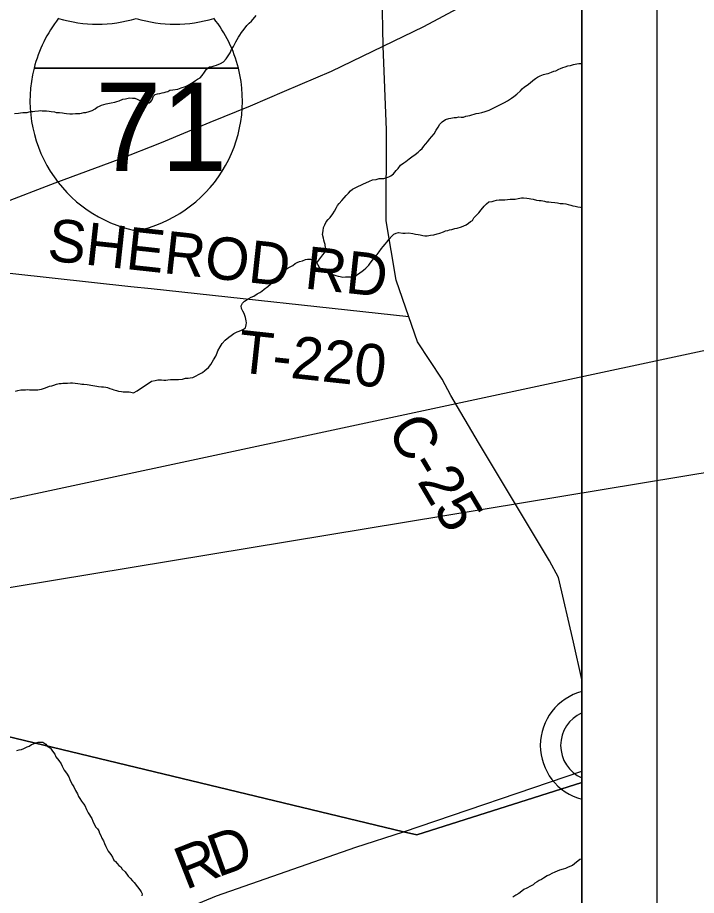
# Model space of a CAD drawing. Extents: x 0.4 to 34.4, y -2.1 to 19.9.
# Drawn here: x 9.045 to 9.953, y 15.384 to 16.558 of the extents above; entities that cross this region are included whole.
import ezdxf

# ---------------------------------------------------------------- set-up
doc = ezdxf.new("R2010")
doc.units = 0
for name, color, linetype in [('GM_X_County', 7, 'Continuous'), ('GM_X_County_Road', 7, 'Continuous'), ('GM_X_County_Road_Text', 7, 'Continuous'), ('GM_X_Interstate_Route', 7, 'Continuous'), ('GM_X_Interstate_Shield', 7, 'Continuous'), ('GM_X_Minor_River', 7, 'Continuous'), ('GM_X_Township', 7, 'Continuous'), ('GM_X_Township_Road', 7, 'Continuous'), ('GM_X_Township_Road_Text', 7, 'Continuous'), ('GM_X_Unincorporated', 7, 'Continuous'), ('SH_Data', 7, 'Continuous')]:
    doc.layers.add(name, color=color, linetype=linetype)

msp = doc.modelspace()

# ---------------------------------------------------------------- linework, layer by layer
at = {"layer": 'GM_X_County'}
msp.add_lwpolyline([(9.8001, 15.3423), (9.8001, 18.8357), (3.0001, 18.8357), (3.0001, 12.0357), (9.5074, 12.0357)], dxfattribs=at)
at = {"layer": 'GM_X_County_Road'}
for points in [[(9.8001, 15.6729), (9.789, 15.7227), (9.7688, 15.8095), (9.7566, 15.8317), (9.6617, 15.9899), (9.6248, 16.0527), (9.613, 16.0746), (9.5801, 16.1244), (9.5685, 16.1577), (9.5514, 16.2068), (9.5383, 16.2863), (9.5386, 16.4082), (9.5341, 16.5199), (9.53, 16.7315)], [(8.2275, 14.9194), (8.32, 14.9606), (8.4596, 15.0199), (8.6764, 15.1154), (8.8642, 15.1959), (9.0381, 15.2705), (9.3113, 15.3835), (9.4976, 15.4487), (9.5613, 15.4693), (9.8001, 15.5501)]]:
    msp.add_lwpolyline(points, dxfattribs=at)
at = {"layer": 'GM_X_Interstate_Route'}
msp.add_lwpolyline([(8.2799, 16.0261), (8.3601, 16.056), (8.441, 16.087), (8.5383, 16.1247), (8.6182, 16.1542), (8.7033, 16.187), (8.7839, 16.218), (8.8633, 16.2483), (8.9432, 16.2782), (9.0238, 16.3096), (9.0956, 16.3369), (9.1811, 16.3686), (9.2375, 16.3911), (9.303, 16.4181), (9.3569, 16.4399), (9.4021, 16.4597), (9.4652, 16.4866), (9.5341, 16.5199), (9.5885, 16.5462), (9.6403, 16.5738)], dxfattribs=at)
at = {"layer": 'GM_X_Interstate_Shield'}
for p, q in [((9.0673, 16.4905), (9.3406, 16.4905)), ((9.3406, 16.4905), (9.0673, 16.4905)), ((9.3406, 16.4905), (9.0673, 16.4905))]:
    msp.add_line(p, q, dxfattribs=at)
for centre, start, end in [((9.2394, 16.447), 141.669, 165.8066), ((9.152, 16.7269), 253.0091, 286.9909), ((9.2558, 16.7269), 253.0091, 286.9909), ((9.1684, 16.447), 14.1934, 38.331), ((9.2394, 16.447), 165.8066, 258.463), ((9.1684, 16.447), 281.537, 14.1934)]:
    msp.add_arc(centre, 0.1776, start, end, dxfattribs=at)
at = {"layer": 'GM_X_Minor_River'}
for points in [[(9.2495, 16.4612), (9.2529, 16.4617), (9.2594, 16.4623), (9.264, 16.4642), (9.2697, 16.466), (9.2727, 16.4675), (9.2758, 16.469), (9.28, 16.4719), (9.2831, 16.4742), (9.2858, 16.4756), (9.2896, 16.4775), (9.2923, 16.4805), (9.2954, 16.485), (9.2977, 16.4891), (9.3019, 16.4921), (9.3054, 16.4928), (9.308, 16.4936), (9.3111, 16.4943), (9.3168, 16.4969), (9.3206, 16.4991), (9.3241, 16.5028), (9.3268, 16.507), (9.3296, 16.5111), (9.3315, 16.5156), (9.3338, 16.5194), (9.3354, 16.522), (9.337, 16.5258), (9.3389, 16.5288), (9.3405, 16.5318), (9.3424, 16.5348), (9.3447, 16.5382), (9.3482, 16.5427), (9.3517, 16.5476), (9.3548, 16.5506), (9.3579, 16.5532), (9.3644, 16.5607)], [(9.7522, 16.4828), (9.7548, 16.4835), (9.7594, 16.4849), (9.7625, 16.4864), (9.7651, 16.4871), (9.769, 16.489), (9.7716, 16.4901), (9.7747, 16.4912), (9.7777, 16.4923), (9.7812, 16.4934), (9.785, 16.4941), (9.7888, 16.4952), (9.7934, 16.4962), (9.796, 16.4966), (9.8001, 16.4968)], [(9.4456, 16.23), (9.4537, 16.2409), (9.4556, 16.2435), (9.4564, 16.2466), (9.4569, 16.2496), (9.4565, 16.2545), (9.4558, 16.2572), (9.4547, 16.2606), (9.4544, 16.2633), (9.4529, 16.2679), (9.4538, 16.2728), (9.4546, 16.2774), (9.4562, 16.2808), (9.4581, 16.2849), (9.4608, 16.2879), (9.4631, 16.2909), (9.467, 16.2958), (9.4693, 16.2992), (9.4717, 16.3041), (9.4732, 16.3067), (9.4752, 16.3093), (9.479, 16.3135), (9.4821, 16.3172), (9.4848, 16.3202), (9.4879, 16.3232), (9.4906, 16.3262), (9.4933, 16.3285), (9.496, 16.3299), (9.5002, 16.3322), (9.5051, 16.3344), (9.5078, 16.3358), (9.5109, 16.3373), (9.5158, 16.3395), (9.52, 16.341), (9.525, 16.3417), (9.5288, 16.3428), (9.5326, 16.3431), (9.5353, 16.3431), (9.5391, 16.3441), (9.5417, 16.3452), (9.5444, 16.3467), (9.5479, 16.3493), (9.5514, 16.3535), (9.5541, 16.3565), (9.5575, 16.3606), (9.5618, 16.3639), (9.5644, 16.3658), (9.569, 16.3692), (9.5725, 16.3718), (9.5771, 16.3751), (9.5809, 16.3781), (9.5836, 16.3807), (9.5863, 16.383), (9.5887, 16.3863), (9.591, 16.389), (9.5941, 16.3923), (9.5964, 16.3953), (9.5995, 16.3991), (9.6026, 16.4025), (9.6053, 16.4074), (9.6076, 16.4115), (9.61, 16.4157), (9.613, 16.4187), (9.6176, 16.4216), (9.6222, 16.4231), (9.6249, 16.4238), (9.6291, 16.4245), (9.6325, 16.4245), (9.6355, 16.4252), (9.6386, 16.4251), (9.6416, 16.4251), (9.6447, 16.4262), (9.65, 16.4273), (9.6527, 16.428), (9.6561, 16.4291), (9.6588, 16.4298), (9.6622, 16.4305), (9.666, 16.4312), (9.6706, 16.4323), (9.6759, 16.4345), (9.6797, 16.4363), (9.6839, 16.4382), (9.6874, 16.44), (9.692, 16.4422), (9.6966, 16.4444), (9.7004, 16.447), (9.7031, 16.4485), (9.7058, 16.4504), (9.7088, 16.4526), (9.713, 16.4556), (9.7177, 16.4601), (9.72, 16.4627), (9.7234, 16.4653), (9.7269, 16.4679), (9.7307, 16.4709), (9.7342, 16.4739), (9.738, 16.4765), (9.7407, 16.4784), (9.7441, 16.4802), (9.7487, 16.4821), (9.7522, 16.4828)], [(9.2159, 16.4436), (9.2182, 16.4432), (9.2213, 16.4443), (9.2236, 16.4458), (9.2252, 16.448), (9.226, 16.4507), (9.2272, 16.4529), (9.2291, 16.4552), (9.2322, 16.4563), (9.2353, 16.4566), (9.2384, 16.4577), (9.2414, 16.458), (9.2441, 16.4587), (9.2464, 16.4594), (9.2487, 16.4609), (9.2495, 16.4612)], [(9.041, 16.4297), (9.0463, 16.4304), (9.049, 16.4307), (9.0521, 16.431), (9.0547, 16.431), (9.0582, 16.4313), (9.0609, 16.432), (9.0635, 16.4324), (9.0658, 16.4327), (9.0681, 16.433), (9.0731, 16.4333), (9.0754, 16.4337), (9.0781, 16.4336), (9.0803, 16.4336), (9.0838, 16.4335), (9.0876, 16.4331), (9.0902, 16.4326), (9.0944, 16.4322), (9.0967, 16.4314), (9.1013, 16.4313), (9.1051, 16.4308), (9.1077, 16.4304), (9.1108, 16.43), (9.1149, 16.4295), (9.1188, 16.4294), (9.1226, 16.4298), (9.126, 16.4297), (9.1283, 16.43), (9.1306, 16.4304), (9.1337, 16.4311), (9.1367, 16.4314), (9.1409, 16.4325), (9.1448, 16.4339), (9.149, 16.4361), (9.1517, 16.4383), (9.1548, 16.4398), (9.1575, 16.4409), (9.1606, 16.442), (9.1637, 16.4427), (9.166, 16.4434), (9.1683, 16.4438), (9.1706, 16.4441), (9.1755, 16.4451), (9.1778, 16.4459), (9.1809, 16.4469), (9.1859, 16.4488), (9.1897, 16.4494), (9.1932, 16.4505), (9.1955, 16.4509), (9.1989, 16.4504), (9.202, 16.4504), (9.205, 16.4488), (9.208, 16.4476), (9.2106, 16.4464), (9.2137, 16.4448), (9.2159, 16.4436)], [(9.5262, 16.2414), (9.5289, 16.2448), (9.532, 16.2493), (9.5344, 16.2519), (9.5371, 16.2549), (9.539, 16.2576), (9.5421, 16.2617), (9.5456, 16.2658), (9.5486, 16.2684), (9.5517, 16.2699), (9.5547, 16.2706), (9.5604, 16.2698), (9.5635, 16.2698), (9.568, 16.2701), (9.5737, 16.2692), (9.5775, 16.2684), (9.5809, 16.268), (9.5836, 16.2676), (9.5873, 16.2668), (9.59, 16.2663), (9.593, 16.2663), (9.5976, 16.267), (9.6018, 16.2677), (9.6064, 16.2688), (9.6098, 16.2699), (9.6151, 16.2717), (9.6178, 16.2728), (9.6205, 16.2735), (9.6231, 16.2742), (9.6262, 16.2749), (9.63, 16.276), (9.6334, 16.2767), (9.6388, 16.2782), (9.6422, 16.2797), (9.6453, 16.2811), (9.6483, 16.283), (9.651, 16.2852), (9.6537, 16.2867), (9.6553, 16.2901), (9.6591, 16.2938), (9.6622, 16.2968), (9.6653, 16.301), (9.6692, 16.3059), (9.6726, 16.3092), (9.6757, 16.3115), (9.6799, 16.3122), (9.6825, 16.3129), (9.6856, 16.314), (9.6894, 16.3143), (9.6936, 16.3146), (9.697, 16.3146), (9.7004, 16.3149), (9.7042, 16.3152), (9.7073, 16.3152), (9.7107, 16.3155), (9.7149, 16.3162), (9.7191, 16.3169), (9.7221, 16.3169), (9.7263, 16.3164), (9.7293, 16.316), (9.7319, 16.3156), (9.735, 16.3152), (9.7395, 16.314), (9.7429, 16.3136), (9.7456, 16.3135), (9.7498, 16.3127), (9.7528, 16.3119), (9.7558, 16.3115), (9.7588, 16.3111), (9.7638, 16.3106), (9.7672, 16.3102), (9.771, 16.3097), (9.7748, 16.3093), (9.7786, 16.3089), (9.7816, 16.3081), (9.7854, 16.3073), (9.788, 16.3065), (9.791, 16.3057), (9.7948, 16.3049), (9.7982, 16.3044), (9.8001, 16.3042)], [(9.2242, 16.0721), (9.2292, 16.0728), (9.233, 16.0735), (9.2379, 16.0738), (9.241, 16.0734), (9.2436, 16.0734), (9.2463, 16.0737), (9.2497, 16.074), (9.2535, 16.074), (9.2565, 16.0739), (9.2603, 16.0743), (9.2657, 16.0746), (9.2699, 16.0757), (9.2733, 16.076), (9.2759, 16.0763), (9.2798, 16.077), (9.2843, 16.0789), (9.2874, 16.0807), (9.2924, 16.0833), (9.2958, 16.0863), (9.3004, 16.09), (9.3035, 16.0942), (9.3055, 16.0972), (9.3074, 16.1002), (9.3102, 16.1055), (9.3121, 16.1096), (9.3129, 16.1123), (9.316, 16.1179), (9.3187, 16.1221), (9.323, 16.1266), (9.3276, 16.1307), (9.3307, 16.1329), (9.3345, 16.1355), (9.3391, 16.1377), (9.3418, 16.1388), (9.3448, 16.1399), (9.3475, 16.1414), (9.3502, 16.1433), (9.351, 16.1471), (9.3514, 16.1497), (9.3511, 16.1524), (9.35, 16.1569), (9.3493, 16.1596), (9.3482, 16.1623), (9.3467, 16.1657), (9.3448, 16.1692), (9.3441, 16.1726), (9.3461, 16.176), (9.3488, 16.179), (9.3545, 16.1823), (9.3576, 16.1842), (9.3614, 16.1856), (9.3656, 16.1886), (9.3691, 16.1905), (9.3717, 16.1923), (9.3752, 16.1949), (9.3798, 16.1983), (9.3837, 16.2017), (9.3875, 16.2054), (9.3906, 16.2088), (9.3944, 16.2114), (9.3975, 16.2144), (9.4006, 16.2181), (9.4033, 16.2207), (9.406, 16.2226), (9.4098, 16.2248), (9.4132, 16.2267), (9.4163, 16.2293), (9.419, 16.2304), (9.4224, 16.2319), (9.4262, 16.2329), (9.4304, 16.2344), (9.4331, 16.2351), (9.4373, 16.2351), (9.4403, 16.2346), (9.4437, 16.2327), (9.4456, 16.23), (9.447, 16.2273), (9.4485, 16.2243), (9.4519, 16.2212), (9.4564, 16.2192), (9.4594, 16.2181), (9.4632, 16.2161), (9.467, 16.2145), (9.4708, 16.213), (9.4738, 16.2122), (9.4768, 16.2117), (9.4802, 16.2109), (9.4837, 16.2113), (9.4871, 16.2112), (9.4912, 16.2112), (9.4943, 16.2115), (9.4977, 16.213), (9.5012, 16.2152), (9.5081, 16.2204), (9.5112, 16.223), (9.515, 16.2271), (9.517, 16.2298), (9.52, 16.2339), (9.5228, 16.2373), (9.5262, 16.2414)], [(9.0426, 16.0587), (9.0456, 16.0595), (9.0495, 16.0601), (9.0533, 16.0605), (9.0556, 16.0604), (9.059, 16.0607), (9.0613, 16.0603), (9.064, 16.0603), (9.0666, 16.0602), (9.0693, 16.0602), (9.0723, 16.0601), (9.0746, 16.0608), (9.0773, 16.0612), (9.0812, 16.0626), (9.0846, 16.0637), (9.0877, 16.0652), (9.0908, 16.0655), (9.0935, 16.0666), (9.0973, 16.068), (9.1007, 16.0687), (9.1034, 16.0687), (9.1057, 16.069), (9.108, 16.0693), (9.1118, 16.0693), (9.116, 16.0696), (9.1187, 16.0695), (9.1221, 16.0691), (9.1259, 16.0686), (9.1289, 16.0682), (9.1312, 16.0678), (9.1339, 16.0677), (9.1381, 16.0673), (9.1411, 16.0668), (9.1434, 16.0664), (9.1487, 16.0656), (9.151, 16.0651), (9.1536, 16.0647), (9.1574, 16.0643), (9.1601, 16.0642), (9.1632, 16.0638), (9.1654, 16.0633), (9.1685, 16.0622), (9.1715, 16.061), (9.1741, 16.0605), (9.1775, 16.0593), (9.1802, 16.0585), (9.184, 16.0581), (9.1863, 16.0576), (9.1886, 16.0576), (9.1909, 16.0576), (9.1943, 16.0575), (9.1969, 16.0571), (9.2004, 16.0562), (9.205, 16.0589), (9.2242, 16.0721)], [(9.0444, 15.5781), (9.0475, 15.5788), (9.0505, 15.5795), (9.0536, 15.5806), (9.0582, 15.5828), (9.0609, 15.5839), (9.0636, 15.5858), (9.0667, 15.5868), (9.0698, 15.5883), (9.0728, 15.589), (9.0755, 15.589), (9.0789, 15.5889), (9.0831, 15.5862), (9.0853, 15.5835), (9.0891, 15.5811), (9.092, 15.5772), (9.095, 15.573), (9.0964, 15.5696), (9.1005, 15.5645), (9.1035, 15.5603), (9.1049, 15.5568), (9.1075, 15.5518), (9.1108, 15.5476), (9.1138, 15.5426), (9.1152, 15.5391), (9.117, 15.5353), (9.1185, 15.5322), (9.1203, 15.5295), (9.1225, 15.5245), (9.1254, 15.5199), (9.1269, 15.5165), (9.1284, 15.5138), (9.1306, 15.5103), (9.1335, 15.5068), (9.135, 15.5042), (9.1376, 15.4992), (9.1394, 15.4946), (9.1445, 15.4869), (9.146, 15.4834), (9.1496, 15.4757), (9.1519, 15.473), (9.1537, 15.4703), (9.1548, 15.4676), (9.1566, 15.4642), (9.1581, 15.4607), (9.1603, 15.4573), (9.1613, 15.4534), (9.1632, 15.4496), (9.1646, 15.4469), (9.1664, 15.4434), (9.1698, 15.4388), (9.172, 15.4353), (9.1738, 15.4315), (9.1764, 15.4296), (9.1805, 15.4242), (9.1831, 15.4222), (9.1853, 15.4191), (9.1891, 15.4156), (9.1931, 15.4098), (9.1958, 15.4071), (9.1987, 15.4037), (9.2013, 15.4013), (9.2058, 15.3955), (9.2088, 15.3917), (9.2106, 15.389), (9.2117, 15.3863), (9.2116, 15.3836)], [(9.8001, 15.4328), (9.7974, 15.4321), (9.7901, 15.4262), (9.7874, 15.4243), (9.7817, 15.4217), (9.7782, 15.4202), (9.7752, 15.4191), (9.7699, 15.4177), (9.7668, 15.4166), (9.7637, 15.4151), (9.7599, 15.4133), (9.7569, 15.4118), (9.7538, 15.4103), (9.7488, 15.4074), (9.7461, 15.4055), (9.7431, 15.404), (9.7404, 15.4022), (9.7373, 15.4007), (9.735, 15.3981), (9.7312, 15.3966), (9.7262, 15.394), (9.7224, 15.3922), (9.7197, 15.3899), (9.7155, 15.3866), (9.7117, 15.3843), (9.7078, 15.3817)]]:
    msp.add_lwpolyline(points, dxfattribs=at)
at = {"layer": 'GM_X_Township'}
msp.add_line((9.8001, 15.3423), (9.8001, 15.535), dxfattribs=at)
for points in [[(9.8001, 15.535), (9.8001, 18.8357), (6.992, 18.8357)], [(6.4528, 16.2176), (7.8323, 15.8856), (7.8807, 15.874), (9.5613, 15.4693), (9.5792, 15.465), (9.8001, 15.535)], [(9.8001, 15.535), (9.5792, 15.465), (9.5613, 15.4693), (7.8807, 15.874), (7.8323, 15.8856), (6.4528, 16.2176)]]:
    msp.add_lwpolyline(points, dxfattribs=at)
at = {"layer": 'GM_X_Township_Road'}
for points in [[(9.2239, 16.1952), (9.1967, 16.1982), (9.0387, 16.2155), (8.9788, 16.222), (8.9641, 16.2237), (8.9471, 16.2277), (8.9421, 16.2333), (8.9444, 16.2425), (8.9494, 16.2473), (8.9566, 16.2476), (8.9579, 16.2465), (8.9624, 16.2423), (8.9703, 16.2254)], [(9.5685, 16.1577), (9.224, 16.1952), (9.2239, 16.1952)]]:
    msp.add_lwpolyline(points, dxfattribs=at)
at = {"layer": 'GM_X_Unincorporated'}
for p, q in [((9.8001, 15.5128), (9.8001, 15.6568)), ((9.8001, 15.5415), (9.8001, 15.6281))]:
    msp.add_line(p, q, dxfattribs=at)
for radius, start, end in [(0.0744, 104.548, 255.452), (0.0472, 113.3447, 246.6553)]:
    msp.add_arc((9.8188, 15.5848), radius, start, end, dxfattribs=at)
at = {"layer": 'SH_Data'}
for p, q in [((9.9001, 18.9357), (9.9001, 11.9357)), ((9.8001, 18.8357), (9.8001, 12.0357))]:
    msp.add_line(p, q, dxfattribs=at)
msp.add_lwpolyline([(10.4047, 16.0223), (10.4047, 16.2068), (6.6239, 15.3979)], close=True, dxfattribs=at)

# ---------------------------------------------------------------- texts
at = {"layer": 'GM_X_County_Road_Text'}
for s, height, rotation, p in [('C-25', 0.05682, 300.6743, (9.5381, 16.0069)), ('D', 0.0568, 19.8543, (9.3129, 15.408)), ('R', 0.0568, 21.4825, (9.2699, 15.3911))]:
    msp.add_text(s, height=height, rotation=rotation, dxfattribs=at).set_placement(p)
at = {"layer": 'GM_X_Interstate_Shield'}
msp.add_text('71', height=0.11837, dxfattribs=at).set_placement((9.1492, 16.3529))
at = {"layer": 'GM_X_Township_Road_Text'}
for s, rotation, p in [('SHEROD RD', 353.7805, (9.0837, 16.2335)), ('T-220', 353.8149, (9.3379, 16.0841))]:
    msp.add_text(s, height=0.05682, rotation=rotation, dxfattribs=at).set_placement(p)

doc.saveas('drawing.dxf')
